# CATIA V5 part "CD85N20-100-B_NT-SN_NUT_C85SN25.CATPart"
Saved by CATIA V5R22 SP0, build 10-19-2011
Part number: CD85N20-100-B_NT-SN_NUT_C85SN25
Revision: ANY
Definition: UNKNOWN
Nomenclature: CD85N20-100-B_NT-SN_NUT_C85SN25
Source: Unknown
Bounding box of the stored display mesh (mm): x -16 to 16, y -18.475 to 18.475, z -5.5 to 5.5
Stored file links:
  U:\S9A\PER\CAO\Assemblage\Reservoir_Flacon\Verin\Poussoir_2\CD85N20-100-B_NT-SN_NUT_C85SN25.CATPart
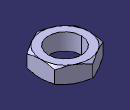
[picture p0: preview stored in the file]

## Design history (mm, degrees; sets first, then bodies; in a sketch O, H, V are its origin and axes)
Body1 "REVOLVE" (main body)
  Solid1: solid without history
